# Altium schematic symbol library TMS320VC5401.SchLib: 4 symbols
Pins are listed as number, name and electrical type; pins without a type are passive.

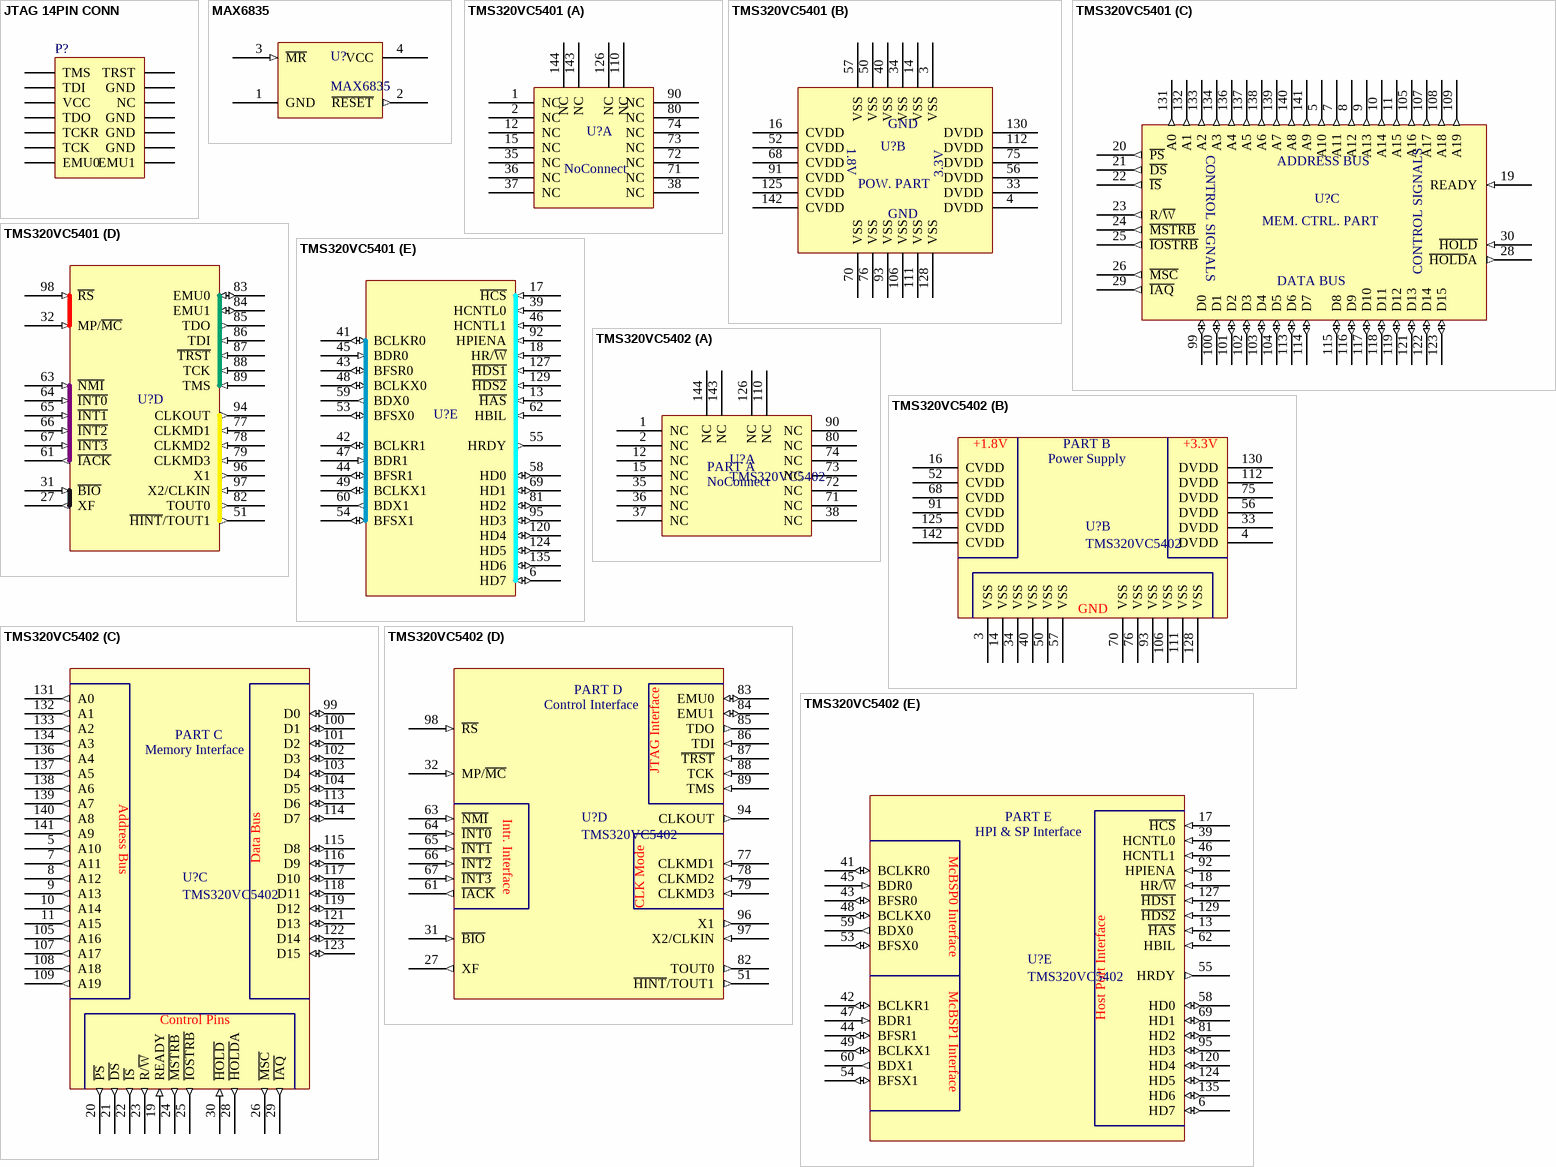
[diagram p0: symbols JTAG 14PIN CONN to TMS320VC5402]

## JTAG 14PIN CONN
designator P?
Header, 7-Pin, Dual row
footprint HDR2X7 (Connector; Header; 7x2 Position)
signal-integrity model Connector
pins: 1 TMS, 2 TRST, 3 TDI, 4 GND, 5 VCC, 6 NC, 7 TDO, 8 GND, 9 TCKR, 10 GND, 11 TCK, 12 GND, 13 EMU0, 14 EMU1

## MAX6835
designator U?
footprint SC70-4 (SOT143, 4-Leads, Body 2.03x2.10mm, Pitch 1.30mm, IPC Medium Density)
pins: 1 GND (power) "SUPPLY_GND", 2 ~{RESET} (out) "RESET SIGNAL", 3 ~{MR} (in) "MANUAL RESET", 4 VCC (power) "VCC 3.3v"

## TMS320VC5401
designator U?
TMS320VC5401
footprint TMS320VC5401_PQFP144 (TSQFP, 144-Leads, Body 20.00x20.00mm, Pitch 0.50mm, IPC Medium Density)
part A pins: 1 NC "NO CONNECT", 2 NC "NO CONNECT", 12 NC "NO CONNECT", 15 NC "NO CONNECT", 35 NC "NO CONNECT", 36 NC "NO CONNECT", 37 NC "NO CONNECT", 38 NC "NO CONNECT", 71 NC "NO CONNECT", 72 NC "NO CONNECT", 73 NC "NO CONNECT", 74 NC "NO CONNECT", 80 NC "NO CONNECT", 90 NC "NO CONNECT", 110 NC "NO CONNECT", 126 NC "NO CONNECT", 143 NC "NO CONNECT", 144 NC "NO CONNECT"
part B pins: 3 VSS (power) "SUPPLY_GND", 4 DVDD (power) "SUPPLY_3.3V", 14 VSS (power) "SUPPLY_GND", 16 CVDD (power) "SUPPLY_1.8V", 33 DVDD (power) "SUPPLY_3.3V", 34 VSS (power) "SUPPLY_GND", 40 VSS (power) "SUPPLY_GND", 50 VSS (power) "SUPPLY_GND", 52 CVDD (power) "SUPPLY_1.8V", 56 DVDD (power) "SUPPLY_3.3V", 57 VSS (power) "SUPPLY_GND", 68 CVDD (power) "SUPPLY_1.8V", 70 VSS (power) "SUPPLY_GND", 75 DVDD (power) "SUPPLY_3.3V", 76 VSS (power) "SUPPLY_GND", 91 CVDD (power) "SUPPLY_1.8V", 93 VSS (power) "SUPPLY_GND", 106 VSS (power) "SUPPLY_GND", 111 VSS (power) "SUPPLY_GND", 112 DVDD (power) "SUPPLY_3.3V", 125 CVDD (power) "SUPPLY_1.8V", 128 VSS (power) "SUPPLY_GND", 130 DVDD (power) "SUPPLY_3.3V", 142 CVDD (power) "SUPPLY_1.8V"
part C pins: 5 A10 (out) "ADDRESS BUS", 7 A11 (out) "ADDRESS BUS", 8 A12 (out) "ADDRESS BUS", 9 A13 (out) "ADDRESS BUS", 10 A14 (out) "ADDRESS BUS", 11 A15 (out) "ADDRESS BUS", 19 READY (in) "CONTROL SIGNALS", 20 ~{PS} (out) "CONTROL SIGNALS", 21 ~{DS} (out) "CONTROL SIGNALS", 22 ~{IS} (out) "CONTROL SIGNALS", 23 R/~{W} (out) "CONTROL SIGNALS", 24 ~{MSTRB} (out) "CONTROL SIGNALS", 25 ~{IOSTRB} (out) "CONTROL SIGNALS", 26 ~{MSC} (out) "CONTROL SIGNALS", 28 ~{HOLD}A (out) "CONTROL SIGNALS", 29 ~{IAQ} (out) "CONTROL SIGNALS", 30 ~{HOLD} (in) "CONTROL SIGNALS", 99 D0 (io) "DATA BUS", 100 D1 (io) "DATA BUS", 101 D2 (io) "DATA BUS", 102 D3 (io) "DATA BUS", 103 D4 (io) "DATA BUS", 104 D5 (io) "DATA BUS", 105 A16 (out) "ADDRESS BUS", 107 A17 (out) "ADDRESS BUS", 108 A18 (out) "ADDRESS BUS", 109 A19 (out) "ADDRESS BUS", 113 D6 (io) "DATA BUS", 114 D7 (io) "DATA BUS", 115 D8 (io) "DATA BUS", 116 D9 (io) "DATA BUS", 117 D10 (io) "DATA BUS", 118 D11 (io) "DATA BUS", 119 D12 (io) "DATA BUS", 121 D13 (io) "DATA BUS", 122 D14 (io) "DATA BUS", 123 D15 (io) "DATA BUS", 131 A0 (out) "ADDRESS BUS", 132 A1 (out) "ADDRESS BUS", 133 A2 (out) "ADDRESS BUS", 134 A3 (out) "ADDRESS BUS", 136 A4 (out) "ADDRESS BUS", 137 A5 (out) "ADDRESS BUS", 138 A6 (out) "ADDRESS BUS", 139 A7 (out) "ADDRESS BUS", 140 A8 (out) "ADDRESS BUS", 141 A9 (out) "ADDRESS BUS"
part D pins: 27 XF (out) "EXTERNAL FLAG OUTPUT", 31 ~{BIO} (in) "BRANCH CONTROL", 32 MP/~{MC} (in) "MICROPROCESSOR/MICROCOMPUTER MODE SELECT", 51 ~{HINT}/TOUT1 (out) "TIMER1 OUTPUT", 61 ~{IACK} (out) "INTERRUPT ACK SIGNAL", 63 ~{NMI} (in) "NONMASKABLE INTERRUPT", 64 ~{INT0} (in) "EXTERNAL INTERRUPT", 65 ~{INT1} (in) "EXTERNAL INTERRUPT", 66 ~{INT2} (in) "EXTERNAL INTERRUPT", 67 ~{INT3} (in) "EXTERNAL INTERRUPT", 77 CLKMD1 (in) "CLOCK MODE SELECT", 78 CLKMD2 (in) "CLOCK MODE SELECT", 79 CLKMD3 (in) "CLOCK MODE SELECT", 82 TOUT0 (out) "TIMER0 OUTPUT", 83 EMU0 (io), 84 EMU1 (io) "EMU0", 85 TDO (out) "TEST OUTPUT", 86 TDI (in) "TEST INPUT", 87 ~{TRST} (in) "TEST RESET", 88 TCK (in) "TEST CLOCK", 89 TMS (in) "TEST MODE SELECT", 94 CLKOUT (out) "MASTER CLOCK OUTPUT", 96 X1 (out) "Output pin from the internal oscillator for the crystal", 97 X2/CLKIN (in) "Oscillator input. This is the input to the on-chip oscillator", 98 ~{RS} (in) "RESET SIGNAL"
part E pins: 6 HD7 (io) "Parallel bidirectional data bus", 13 ~{HAS} (in) "Address strobe", 17 ~{HCS} (in) "Chip select", 18 HR/~{W} (in) "Read/write", 39 HCNTL0 (in) "Control", 41 BCLKR0 (io) "RECEIVE CLOCK INPUT", 42 BCLKR1 (io) "RECEIVE CLOCK INPUT", 43 BFSR0 (io) "Frame synchronization pulse for receive input", 44 BFSR1 (io) "Frame synchronization pulse for receive input", 45 BDR0 (in) "SERIAL DATA RECEIVE INPUT", 46 HCNTL1 (in) "Control", 47 BDR1 (in) "SERIAL DATA RECEIVE INPUT", 48 BCLKX0 (io) "Transmit clock", 49 BCLKX1 (io) "Transmit clock", 53 BFSX0 (io) "Frame synchronization pulse for transmit input/output", 54 BFSX1 (io) "Frame synchronization pulse for transmit input/output", 55 HRDY (out) "Ready", 58 HD0 (io) "Parallel bidirectional data bus", 59 BDX0 (out) "Serial data transmit output", 60 BDX1 (out) "Serial data transmit output", 62 HBIL (in) "Byte identification", 69 HD1 (io) "Parallel bidirectional data bus", 81 HD2 (io) "Parallel bidirectional data bus", 92 HPIENA (in) "HPI module select", 95 HD3 (io) "Parallel bidirectional data bus", 120 HD4 (io) "Parallel bidirectional data bus", 124 HD5 (io) "Parallel bidirectional data bus", 127 ~{HDS1} (in) "Data strobe", 129 ~{HDS2} (in) "Data strobe", 135 HD6 (io) "Parallel bidirectional data bus"

## TMS320VC5402
designator U?
footprint TMS320VC5401_PQFP144 (TSQFP, 144-Leads, Body 20.00x20.00mm, Pitch 0.50mm, IPC Medium Density)
part A pins: 1 NC "NO CONNECT", 2 NC "NO CONNECT", 12 NC "NO CONNECT", 15 NC "NO CONNECT", 35 NC "NO CONNECT", 36 NC "NO CONNECT", 37 NC "NO CONNECT", 38 NC "NO CONNECT", 71 NC "NO CONNECT", 72 NC "NO CONNECT", 73 NC "NO CONNECT", 74 NC "NO CONNECT", 80 NC "NO CONNECT", 90 NC "NO CONNECT", 110 NC "NO CONNECT", 126 NC "NO CONNECT", 143 NC "NO CONNECT", 144 NC "NO CONNECT"
part B pins: 3 VSS (power) "SUPPLY_GND", 4 DVDD (power) "SUPPLY_3.3V", 14 VSS (power) "SUPPLY_GND", 16 CVDD (power) "SUPPLY_1.8V", 33 DVDD (power) "SUPPLY_3.3V", 34 VSS (power) "SUPPLY_GND", 40 VSS (power) "SUPPLY_GND", 50 VSS (power) "SUPPLY_GND", 52 CVDD (power) "SUPPLY_1.8V", 56 DVDD (power) "SUPPLY_3.3V", 57 VSS (power) "SUPPLY_GND", 68 CVDD (power) "SUPPLY_1.8V", 70 VSS (power) "SUPPLY_GND", 75 DVDD (power) "SUPPLY_3.3V", 76 VSS (power) "SUPPLY_GND", 91 CVDD (power) "SUPPLY_1.8V", 93 VSS (power) "SUPPLY_GND", 106 VSS (power) "SUPPLY_GND", 111 VSS (power) "SUPPLY_GND", 112 DVDD (power) "SUPPLY_3.3V", 125 CVDD (power) "SUPPLY_1.8V", 128 VSS (power) "SUPPLY_GND", 130 DVDD (power) "SUPPLY_3.3V", 142 CVDD (power) "SUPPLY_1.8V"
part C pins: 5 A10 (out) "ADDRESS BUS", 7 A11 (out) "ADDRESS BUS", 8 A12 (out) "ADDRESS BUS", 9 A13 (out) "ADDRESS BUS", 10 A14 (out) "ADDRESS BUS", 11 A15 (out) "ADDRESS BUS", 19 READY (in) "CONTROL SIGNALS", 20 ~{PS} (out) "CONTROL SIGNALS", 21 ~{DS} (out) "CONTROL SIGNALS", 22 ~{IS} (out) "CONTROL SIGNALS", 23 R/~{W} (out) "CONTROL SIGNALS", 24 ~{MSTRB} (out) "CONTROL SIGNALS", 25 ~{IOSTRB} (out) "CONTROL SIGNALS", 26 ~{MSC} (out) "CONTROL SIGNALS", 28 ~{HOLD}A (out) "CONTROL SIGNALS", 29 ~{IAQ} (out) "CONTROL SIGNALS", 30 ~{HOLD} (in) "CONTROL SIGNALS", 99 D0 (io) "DATA BUS", 100 D1 (io) "DATA BUS", 101 D2 (io) "DATA BUS", 102 D3 (io) "DATA BUS", 103 D4 (io) "DATA BUS", 104 D5 (io) "DATA BUS", 105 A16 (out) "ADDRESS BUS", 107 A17 (out) "ADDRESS BUS", 108 A18 (out) "ADDRESS BUS", 109 A19 (out) "ADDRESS BUS", 113 D6 (io) "DATA BUS", 114 D7 (io) "DATA BUS", 115 D8 (io) "DATA BUS", 116 D9 (io) "DATA BUS", 117 D10 (io) "DATA BUS", 118 D11 (io) "DATA BUS", 119 D12 (io) "DATA BUS", 121 D13 (io) "DATA BUS", 122 D14 (io) "DATA BUS", 123 D15 (io) "DATA BUS", 131 A0 (out) "ADDRESS BUS", 132 A1 (out) "ADDRESS BUS", 133 A2 (out) "ADDRESS BUS", 134 A3 (out) "ADDRESS BUS", 136 A4 (out) "ADDRESS BUS", 137 A5 (out) "ADDRESS BUS", 138 A6 (out) "ADDRESS BUS", 139 A7 (out) "ADDRESS BUS", 140 A8 (out) "ADDRESS BUS", 141 A9 (out) "ADDRESS BUS"
part D pins: 27 XF (out) "EXTERNAL FLAG OUTPUT", 31 ~{BIO} (in) "BRANCH CONTROL", 32 MP/~{MC} (in) "MICROPROCESSOR/MICROCOMPUTER MODE SELECT", 51 ~{HINT}/TOUT1 (out) "TIMER1 OUTPUT", 61 ~{IACK} (out) "INTERRUPT ACK SIGNAL", 63 ~{NMI} (in) "NONMASKABLE INTERRUPT", 64 ~{INT0} (in) "EXTERNAL INTERRUPT", 65 ~{INT1} (in) "EXTERNAL INTERRUPT", 66 ~{INT2} (in) "EXTERNAL INTERRUPT", 67 ~{INT3} (in) "EXTERNAL INTERRUPT", 77 CLKMD1 (in) "CLOCK MODE SELECT", 78 CLKMD2 (in) "CLOCK MODE SELECT", 79 CLKMD3 (in) "CLOCK MODE SELECT", 82 TOUT0 (out) "TIMER0 OUTPUT", 83 EMU0 (io), 84 EMU1 (io) "EMU0", 85 TDO (out) "TEST OUTPUT", 86 TDI (in) "TEST INPUT", 87 ~{TRST} (in) "TEST RESET", 88 TCK (in) "TEST CLOCK", 89 TMS (in) "TEST MODE SELECT", 94 CLKOUT (out) "MASTER CLOCK OUTPUT", 96 X1 (out) "Output pin from the internal oscillator for the crystal", 97 X2/CLKIN (in) "Oscillator input. This is the input to the on-chip oscillator", 98 ~{RS} (in) "RESET SIGNAL"
part E pins: 6 HD7 (io) "Parallel bidirectional data bus", 13 ~{HAS} (in) "Address strobe", 17 ~{HCS} (in) "Chip select", 18 HR/~{W} (in) "Read/write", 39 HCNTL0 (in) "Control", 41 BCLKR0 (io) "RECEIVE CLOCK INPUT", 42 BCLKR1 (io) "RECEIVE CLOCK INPUT", 43 BFSR0 (io) "Frame synchronization pulse for receive input", 44 BFSR1 (io) "Frame synchronization pulse for receive input", 45 BDR0 (in) "SERIAL DATA RECEIVE INPUT", 46 HCNTL1 (in) "Control", 47 BDR1 (in) "SERIAL DATA RECEIVE INPUT", 48 BCLKX0 (io) "Transmit clock", 49 BCLKX1 (io) "Transmit clock", 53 BFSX0 (io) "Frame synchronization pulse for transmit input/output", 54 BFSX1 (io) "Frame synchronization pulse for transmit input/output", 55 HRDY (out) "Ready", 58 HD0 (io) "Parallel bidirectional data bus", 59 BDX0 (out) "Serial data transmit output", 60 BDX1 (out) "Serial data transmit output", 62 HBIL (in) "Byte identification", 69 HD1 (io) "Parallel bidirectional data bus", 81 HD2 (io) "Parallel bidirectional data bus", 92 HPIENA (in) "HPI module select", 95 HD3 (io) "Parallel bidirectional data bus", 120 HD4 (io) "Parallel bidirectional data bus", 124 HD5 (io) "Parallel bidirectional data bus", 127 ~{HDS1} (in) "Data strobe", 129 ~{HDS2} (in) "Data strobe", 135 HD6 (io) "Parallel bidirectional data bus"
